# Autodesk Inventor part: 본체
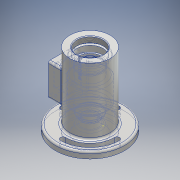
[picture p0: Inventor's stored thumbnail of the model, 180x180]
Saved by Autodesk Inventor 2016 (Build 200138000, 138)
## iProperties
Created: 2017-05
Part Number: 본체
Material: 알루미늄 6061
Document SubType Name: Modeling
Designer: USER
Density: 2.7 g/cm^3
Appearance: 알루미늄 - 평지
Mass: 677.06 g
Surface Area: 624.507 cm^2
Volume: 250.763 cm^3
Author: USER
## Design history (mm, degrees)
sketch "스케치1"
  geometry: C1 r 31 at (0, 0); 1 further point
  constraints: 1 centre point, 1 coincident
  dimensions: "d0" = 62 diameter of C1
extrude "돌출1" new body sketch "스케치1" distance "d1" = 115; taper "d2" = 0 deg
node "작업 평면1"
sketch "스케치2"
  geometry: C1 r 53 at (0, 0); 1 further point
  constraints: 1 centre point, 1 coincident
  dimensions: "d4" = 106 diameter of C1
extrude "돌출2" join sketch "스케치2" distance "d5" = 10; taper "d6" = 0 deg
sketch "스케치3"
  geometry: 1 further point
hole "구멍1" sketch "스케치3" at (0, 0) diameter "d7" = 40.376; stored, may be unused: countersink angle "d11" = 90 deg, drill point angle "d13" = 118 deg; dims "d8" = 9, "d9" = 4, "d10" = 2, "d12" = 9
node "작업 평면2"
sketch "스케치4"
  geometry: L1 (-20.188, 115)-(20.188, 115) reference; L2 (-31, 0)-(31, 0) reference; L3 (0, 115)-(0, 0); L4 (20.188, 106)-(-20.188, 106) reference; L5 (0, 106)-(24, 106); L6 (24, 106)-(24, 103); L7 (24, 103)-(20, 103); L8 (20, 103)-(20, 94); L9 (20, 94)-(17.5, 94); L10 (17.5, 94)-(17.5, 90.75); L11 (17.5, 90.75)-(18.5, 90.75); L12 (18.5, 89)-(17.5, 89); L13 (17.5, 89)-(17.5, 78); L14 (17.5, 78)-(26, 78); L15 (26, 78)-(26, 40); L16 (26, 40)-(17.5, 40); L17 (17.5, 40)-(17.5, 29.3); L18 (17.2, 29)-(16.5, 29); L19 (16.5, 29)-(16.5, 27); L20 (13.5, 24)-(10, 24); L21 (10, 24)-(10, 21.3); L22 (17.248, 12.097)-(22, 0); L23 (18.5, 90.75)-(18.5, 89); L24 (10, 21.3)-(12.2, 21.3); L25 (12.5, 21)-(12.5, 14); L26 (31, 13)-(-31, 13) reference; L27 (14.571, 14)-(14.471, 14); L28 (17.248, 12.097)-(22, 0); L29 (14.455, 14)-(12.5, 14); A1 r 0.3 centre (12.2, 21) between (12.5, 21) and (12.2, 21.3); A2 r 3 centre (13.5, 27) between (13.5, 24) and (16.5, 27); A3 r 0.3 centre (17.2, 29.3) between (17.2, 29) and (17.5, 29.3); A4 r 3 centre (14.455, 11) between (17.248, 12.097) and (14.455, 14); 5 further points
  constraints: 50 end point, 14 perpendicular, 14 point on line, 8 point on circle, 8 tangent, 6 horizontal, 4 centre point, 2 midpoint, 2 vertical, 1 collinear
  dimensions: "d15" = 3 distance of L5.end L6.end; "d16" = 21 distance between parallel lines of L9 L1; "d17" = 38 distance between parallel lines of L16 L14; "d19" = 11 distance of L16.end point (17.5, 29); "d20" = 5 distance of L18.end point (16.5, 24); "d21" = 24 vertical distance of L22.end point (16.5, 24); "d23" = 1.75 distance of L11.end L12.start; "d24" = 26 distance between parallel lines of L12 L1; "d25" = 48 diameter of L6 L3; "d26" = 40 diameter of L8 L3; "d27" = 35 diameter of L10 L3; "d28" = 37 diameter of L23 L3; "d29" = 35 diameter of L13 L3; "d30" = 52 diameter of L15 L3; "d31" = 35 diameter of L17 L3; "d32" = 33 diameter of L19 L3; "d33" = 20 diameter of L21 L3; "d34" = 25 diameter of L25 L3; "d37" = 44 diameter of L22.end L3; "d38" = 0.3 radius of A1; "d39" = 3 radius of A2; "d41" = 2.7 distance of L20.end L21.end; "d87" = 0.3 radius of A3; "d110" = 14 distance from line of point (16.5, 14) L2; "d112" = 3 radius of A4
revolve "회전1" stored, may be unused: angle "d43" = 90 deg
node "작업 평면3"
sketch "스케치5"
  geometry: L1 (31, 115)-(-31, 115) reference; L2 (53, 13)-(-53, 13) reference; L3 (20, 84)-(-20, 84); L4 (-20, 84)-(-20, 34); L5 (-20, 34)-(20, 34); L6 (20, 34)-(20, 84); L7 (20, 84)-(-20, 34); L8 (-20, 84)-(20, 34); L9 (11, 75)-(-11, 75); L10 (-11, 75)-(-11, 43); L11 (-11, 43)-(11, 43); L12 (11, 43)-(11, 75); L13 (11, 75)-(-11, 43); L14 (-11, 75)-(11, 43); 4 further points
  constraints: 24 end point, 6 midpoint, 4 parallel, 2 horizontal, 2 perpendicular, 1 vertical alignment
  dimensions: "d45" = 56 distance from line of point (0, 59) L1; "d46" = 40 distance between parallel lines of L6 L4; "d47" = 50 distance between parallel lines of L5 L3; "d48" = 22 distance of L10.end L11.end; "d49" = 32 distance of L11.end L9.start
extrude "돌출3" join sketch "스케치5" stored distance "d50" = 10; taper "d51" = 0 deg
sketch "스케치6"
  geometry: 1 further point
extrude "돌출4" cut sketch "스케치5" distance "d52" = 20; taper "d53" = 0 deg
sketch "스케치7"
  geometry: L1 (84, 20)-(84, -20) reference; L2 (75, 11)-(75, -11) reference; L3 (115, -31)-(115, 31) reference; L4 (13, -31)-(13, 31) reference; L5 (34, 20)-(84, 20) reference; L6 (84, 20)-(84, -20) reference; L7 (84, -20)-(34, -20) reference; L8 (34, -20)-(34, 20) reference; 5 further points
  dimensions: "d54" = 41 distance of point (38.5, -15.358) point (79.5, -15.5); "d56" = 15.5 vertical distance of point (0, 0) point (79.5, -15.5); "d57" = 4.5 distance from line of point (79.5, -15.5) L1; "d58" = 31 distance of point (38.5, 15.642) point (38.5, -15.358); "d59" = 41 distance of point (38.5, 15.642) point (79.5, 15.5); "d60" = 31 distance of point (79.5, 15.5) point (79.5, -15.5); "d61" = 4.5 distance from line of point (79.5, 15.5) L1; "d62" = 4.50024 distance from line of L8 point (38.5, -15.358)
  node "투영된 루프1"
hole "구멍2" sketch "스케치7" diameter "d63" = 2.459; stored, may be unused: countersink angle "d67" = 90 deg, drill point angle "d69" = 118 deg; dims "d64" = 6, "d65" = 4, "d66" = 2, "d68" = 8
hole "구멍3" sketch "스케치7" diameter "d70" = 2.459; stored, may be unused: countersink angle "d74" = 90 deg, drill point angle "d76" = 118 deg; dims "d71" = 6, "d72" = 4, "d73" = 2, "d75" = 8
sketch "스케치8"
  geometry: L1 (0, 0)-(53, 0); C1 r 31 at (0, 0) reference; A1 r 41.5 centre (0, 0) between (41.5, 0) and (0, 41.5); A2 r 4 centre (41.5, 0) between (37.5, 0) and (45.5, 0); A3 r 4 centre (0, 41.5) between (0, 45.5) and (0, 37.5); A4 r 4 centre (0, -41.5) between (0, -45.5) and (0, -37.5); A5 r 4 centre (-41.5, 0) between (-37.5, 0) and (-45.5, 0); A6 r 37.5 centre (0, 0) between (-37.5, 0) and (0, -37.5); A7 r 37.5 centre (0, 0) between (37.5, 0) and (0, 37.5); A8 r 45.5 centre (0, 0) between (-45.5, 0) and (0, -45.5); A9 r 45.5 centre (0, 0) between (45.5, 0) and (0, 45.5); 2 further points
  constraints: 20 point on circle, 9 centre point, 3 coincident, 3 point on line, 2 end point, 2 horizontal alignment, 2 vertical alignment, 1 horizontal, 1 tangent, 1 other
  dimensions: "d77" = 83 diameter of A1; "d80" = 8 diameter of A2; "d81" = 8 diameter of A3; "d82" = 8 diameter of A4; "d83" = 8 diameter of A5; "d84" = 8 radial gap between concentric circles of A8 A6
extrude "돌출5" cut sketch "스케치8" stored distance "d85" = 20; taper "d86" = 0 deg
fillet "모깎기1" dims "d90" = 3
fillet "모깎기2" dims "d91" = 3
chamfer "모따기1" distance "d93" = 1; stored, may be unused: second distance "d94" = 2, angle "d95" = 45 deg
fillet "모깎기4" dims "d96" = 3
fillet "모깎기5" dims "d97" = 3
sketch "스케치9"
  geometry: 1 further point
node "작업 평면4"
sketch "스케치10"
  geometry: L1 (13, -34)-(75, -34) reference; L2 (0, 44)-(0, 0) reference; 2 further points
  constraints: 1 other
  dimensions: "d99" = 56 distance from line of point (8, 22) L1; "d100" = 8 distance from line of L2 point (8, 22)
feature "엠보싱1" sketch "스케치10" dims "d0" = 62, "d15" = 3, "d16" = 21, "d17" = 38, "d19" = 11, "d20" = 5, "d21" = 24, "d23" = 1.75, "d24" = 26, "d25" = 48, "d26" = 40, "d27" = 35, "d28" = 37, "d29" = 35, "d30" = 52, "d31" = 35, "d32" = 33, "d33" = 20, "d34" = 25, "d37" = 44, "d38" = 0.3, "d39" = 3, "d41" = 2.7, "d87" = 0.3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
sketch "스케치11"
  geometry: L1 (53, 10)-(53, 3) reference; L2 (53, 3)-(45.5, 3) reference; L3 (45.5, 3)-(45.5, 13) reference; L4 (45.5, 13)-(50, 13) reference; L5 (-50, 13)-(-45.5, 13) reference; L6 (-45.5, 13)-(-45.5, 3) reference; L7 (-45.5, 3)-(-53, 3) reference; L8 (-53, 3)-(-53, 10) reference; L9 (17.5, 78)-(17.5, 89) reference; L10 (17.5, 89)-(18.5, 89) reference; L11 (18.5, 89)-(18.5, 90.75) reference; L12 (18.5, 90.75)-(17.5, 90.75) reference; L13 (17.5, 90.75)-(17.5, 94) reference; L14 (17.5, 94)-(20, 94) reference; L15 (20, 94)-(20, 103) reference; L16 (20, 103)-(24, 103) reference; L17 (24, 103)-(24, 106) reference; L18 (24, 106)-(20.188, 106) reference; L19 (20.188, 106)-(20.188, 114) reference; L20 (20.188, 114)-(21.188, 115) reference; L21 (21.188, 115)-(31, 115) reference; L22 (31, 115)-(31, 87) reference; L23 (34, 84)-(44, 84) reference; L24 (44, 84)-(44, 75) reference; L25 (44, 75)-(26, 75) reference; L26 (26, 75)-(26, 78) reference; L27 (26, 78)-(17.5, 78) reference; L28 (12.5, 14)-(12.5, 21) reference; L29 (12.2, 21.3)-(10, 21.3) reference; L30 (10, 21.3)-(10, 24) reference; L31 (10, 24)-(13.5, 24) reference; L32 (16.5, 27)-(16.5, 29) reference; L33 (16.5, 29)-(17.2, 29) reference; L34 (17.5, 29.3)-(17.5, 40) reference; L35 (17.5, 40)-(26, 40) reference; L36 (26, 40)-(26, 43) reference; L37 (26, 43)-(44, 43) reference; L38 (44, 43)-(44, 34) reference; L39 (44, 34)-(34, 34) reference; L40 (31, 31)-(31, 16) reference; L41 (34, 13)-(37.5, 13) reference; L42 (37.5, 13)-(37.5, 3) reference; L43 (37.5, 3)-(31, 3) reference; L44 (31, 3)-(31, 0) reference; L45 (31, 0)-(22, 0) reference; L46 (-31, 0)-(-31, 3) reference; L47 (-31, 3)-(-37.5, 3) reference; L48 (-37.5, 3)-(-37.5, 13) reference; L49 (-37.5, 13)-(-34, 13) reference; L50 (-31, 16)-(-31, 115) reference; L51 (-31, 115)-(-21.188, 115) reference; L52 (-21.188, 115)-(-20.188, 114) reference; L53 (-20.188, 114)-(-20.188, 106) reference; L54 (-20.188, 106)-(-24, 106) reference; L55 (-24, 106)-(-24, 103) reference; L56 (-24, 103)-(-20, 103) reference; L57 (-20, 103)-(-20, 94) reference; L58 (-20, 94)-(-17.5, 94) reference; L59 (-17.5, 94)-(-17.5, 90.75) reference; L60 (-17.5, 90.75)-(-18.5, 90.75) reference; L61 (-18.5, 90.75)-(-18.5, 89) reference; L62 (-18.5, 89)-(-17.5, 89) reference; L63 (-17.5, 89)-(-17.5, 78) reference; L64 (-17.5, 78)-(-26, 78) reference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; A1 r 3 centre (50, 10) between (53, 10) and (50, 13) reference; A2 r 3 centre (-50, 10) between (-50, 13) and (-53, 10) reference; A3 r 3 centre (34, 87) between (31, 87) and (34, 84) reference; A4 r 0.3 centre (12.2, 21) between (12.5, 21) and (12.2, 21.3) reference; A5 r 3 centre (13.5, 27) between (13.5, 24) and (16.5, 27) reference; A6 r 0.3 centre (17.2, 29.3) between (17.2, 29) and (17.5, 29.3) reference; A7 r 3 centre (34, 31) between (34, 34) and (31, 31) reference; A8 r 3 centre (34, 16) between (31, 16) and (34, 13) reference; A9 r 3 centre (-34, 16) between (-34, 13) and (-31, 16) reference; A10 r 0.3 centre (-17.2, 29.3) between (-17.5, 29.3) and (-17.2, 29) reference; A11 r 3 centre (-13.5, 27) between (-16.5, 27) and (-13.5, 24) reference; A12 r 0.3 centre (-12.2, 21) between (-12.2, 21.3) and (-12.5, 21) reference; A13 r 3 centre (14.455, 11) between (17.248, 12.097) and (14.455, 14) reference; A14 r 3 centre (-14.455, 11) between (-14.455, 14) and (-17.248, 12.097) reference; 1 further point
  node "절단 모서리 투영1"
sketch "스케치12"
  geometry: 1 further point
revolve "회전2" stored, may be unused: angle "d103" = 90 deg
fillet "모깎기6" dims "d104" = 3
fillet "모깎기8" dims "d106" = 3
chamfer "모따기2" distance "d107" = 1; stored, may be unused: second distance "d108" = 2, angle "d109" = 45 deg
fillet "모깎기9" dims "d113" = 3
node "솔리드1"
node "투영된 루프2"
other parameters: "d3" = -3, "d14" = 0, "d44" = -44, "d78" = 75, "d79" = 91, "d98" = 18.25
